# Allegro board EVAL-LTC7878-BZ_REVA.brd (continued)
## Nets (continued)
UNNAMED_3_ADLTC7878V2_I47_SW1: C82.2(N2) M17.1 M17.2 M17.3(S3) M18.5 M18.6 M18.7 M18.8 M21.1 M21.2 M21.3(S3) M22.5 M22.6 M22.7 M22.8 R79.1 R80.1 R81.1 U3.45
UNNAMED_3_ADLTC7878V2_I47_SW2: C85.1 L3.2(N2) M19.5 M19.6 M19.7 M19.8 M20.1 M20.2 M20.3(S3) M23.5 M23.6 M23.7 M23.8 M24.1 M24.2 M24.3(S3) R89.1 U3.16
UNNAMED_3_ADLTC7878V2_I47_TG1: R75.2(N2) U3.47
UNNAMED_3_ADLTC7878V2_I47_TG2: R97.2(N2) U3.14
UNNAMED_3_ADLTC7878V2_I47_VIN: C78.1 R73.2(N2) U3.4
UNNAMED_3_ADLTC7878V2_I47_VOUT: R94.2(N2) R98.1 U3.38(VOUT)
UNNAMED_3_CAP_I32_N1: C81.1 R78.2(N2)
UNNAMED_3_CAP_I94_N2: C88.2(N2) R96.2(N2) R100.1 TP47.1(N1)
UNNAMED_3_IND_I85_N1: L3.1 R80.2(N2) R81.2(N2) R82.1 R85.1
UNNAMED_3_NCTESTPAD_I107_N1: R102.2(N2) R103.1 TP54.1(N1)
UNNAMED_3_RES_I65_N1: M17.4 M21.4 R75.1
UNNAMED_3_RES_I66_N1: M18.4 M22.4 R76.1
UNNAMED_3_RES_I80_N1: M19.4 M23.4 R95.1
UNNAMED_3_RES_I109_N1: M20.4 M24.4 R97.1
UNNAMED_4_ADLTC7878V2_I126_BG1: R109.2(N2) U4.1
UNNAMED_4_ADLTC7878V2_I126_BG2: R128.2(N2) U4.12
UNNAMED_4_ADLTC7878V2_I126_BOOST1: C115.1 D7.C U4.46
UNNAMED_4_ADLTC7878V2_I126_BOOST2: C118.2(N2) D8.C U4.15
UNNAMED_4_ADLTC7878V2_I126_CSN: R129.1 TP62.1(N1) U4.35
UNNAMED_4_ADLTC7878V2_I126_CSP: C121.1 R132.1 TP67.1(N1) U4.34
UNNAMED_4_ADLTC7878V2_I126_EXTVCC: C119.1 R127.1 TP63.1(N1) U4.8
UNNAMED_4_ADLTC7878V2_I126_FREQ: R117.1 U4.28
UNNAMED_4_ADLTC7878V2_I126_ISNSD: C116.1 R116.1 R120.1 U4.43
UNNAMED_4_ADLTC7878V2_I126_ISNSN: C117.2(N2) R115.2(N2) R120.2(N2) R122.2(N2) U4.41
UNNAMED_4_ADLTC7878V2_I126_ISNSP: C116.2(N2) C117.1 R112.2(N2) R116.2(N2) R118.2(N2) U4.42
UNNAMED_4_ADLTC7878V2_I126_ITHB: R110.2(N2) U4.21
UNNAMED_4_ADLTC7878V2_I126_MODE: R121.1 R125.1 U4.26
UNNAMED_4_ADLTC7878V2_I126_PGOOD: R126.1 TP66.1(N1) U4.19
UNNAMED_4_ADLTC7878V2_I126_PHASMD: R123.1 R124.1 U4.27
UNNAMED_4_ADLTC7878V2_I126_SETCUR: R119.1 U4.31
UNNAMED_4_ADLTC7878V2_I126_SW1: C115.2(N2) M25.1 M25.2 M25.3(S3) M26.5 M26.6 M26.7 M26.8 M29.1 M29.2 M29.3(S3) M30.5 M30.6 M30.7 M30.8 R112.1 R113.1 R114.1 U4.45
UNNAMED_4_ADLTC7878V2_I126_SW2: C118.1 L4.2(N2) M27.5 M27.6 M27.7 M27.8 M28.1 M28.2 M28.3(S3) M31.5 M31.6 M31.7 M31.8 M32.1 M32.2 M32.3(S3) R122.1 U4.16
UNNAMED_4_ADLTC7878V2_I126_TG1: R108.2(N2) U4.47
UNNAMED_4_ADLTC7878V2_I126_TG2: R130.2(N2) U4.14
UNNAMED_4_ADLTC7878V2_I126_VIN: C111.1 R106.2(N2) U4.4
UNNAMED_4_ADLTC7878V2_I126_VOUT: R127.2(N2) R131.1 U4.38(VOUT)
UNNAMED_4_CAP_I32_N1: C114.1 R111.2(N2)
UNNAMED_4_CAP_I93_N2: C121.2(N2) R129.2(N2) R133.1 TP64.1(N1)
UNNAMED_4_IND_I84_N1: L4.1 R113.2(N2) R114.2(N2) R115.1 R118.1
UNNAMED_4_NCTESTPAD_I106_N1: R135.2(N2) R136.1 TP71.1(N1)
UNNAMED_4_RES_I64_N1: M25.4 M29.4 R108.1
UNNAMED_4_RES_I65_N1: M26.4 M30.4 R109.1
UNNAMED_4_RES_I79_N1: M27.4 M31.4 R128.1
UNNAMED_4_RES_I108_N1: M28.4 M32.4 R130.1
UNNAMED_5_ADLTC7878V2_I47_BG1: R142.2(N2) U5.1
UNNAMED_5_ADLTC7878V2_I47_BG2: R161.2(N2) U5.12
UNNAMED_5_ADLTC7878V2_I47_BOOST1: C148.1 D9.C U5.46
UNNAMED_5_ADLTC7878V2_I47_BOOST2: C151.2(N2) D10.C U5.15
UNNAMED_5_ADLTC7878V2_I47_CSN: R162.1 TP79.1(N1) U5.35
UNNAMED_5_ADLTC7878V2_I47_CSP: C154.1 R165.1 TP84.1(N1) U5.34
UNNAMED_5_ADLTC7878V2_I47_EXTVCC: C152.1 R160.1 TP80.1(N1) U5.8
UNNAMED_5_ADLTC7878V2_I47_FREQ: R150.1 U5.28
UNNAMED_5_ADLTC7878V2_I47_ISNSD: C149.1 R149.1 R153.1 U5.43
UNNAMED_5_ADLTC7878V2_I47_ISNSN: C150.2(N2) R148.2(N2) R153.2(N2) R155.2(N2) U5.41
UNNAMED_5_ADLTC7878V2_I47_ISNSP: C149.2(N2) C150.1 R145.2(N2) R149.2(N2) R151.2(N2) U5.42
UNNAMED_5_ADLTC7878V2_I47_ITHB: R143.2(N2) U5.21
UNNAMED_5_ADLTC7878V2_I47_MODE: R154.1 R158.1 U5.26
UNNAMED_5_ADLTC7878V2_I47_PGOOD: R159.1 TP83.1(N1) U5.19
UNNAMED_5_ADLTC7878V2_I47_PHASMD: R156.1 R157.1 U5.27
UNNAMED_5_ADLTC7878V2_I47_SETCUR: R152.1 U5.31
UNNAMED_5_ADLTC7878V2_I47_SW1: C148.2(N2) M33.1 M33.2 M33.3(S3) M34.5 M34.6 M34.7 M34.8 M37.1 M37.2 M37.3(S3) M38.5 M38.6 M38.7 M38.8 R145.1 R146.1 R147.1 U5.45
UNNAMED_5_ADLTC7878V2_I47_SW2: C151.1 L5.2(N2) M35.5 M35.6 M35.7 M35.8 M36.1 M36.2 M36.3(S3) M39.5 M39.6 M39.7 M39.8 M40.1 M40.2 M40.3(S3) R155.1 U5.16
UNNAMED_5_ADLTC7878V2_I47_TG1: R141.2(N2) U5.47
UNNAMED_5_ADLTC7878V2_I47_TG2: R163.2(N2) U5.14
UNNAMED_5_ADLTC7878V2_I47_VIN: C144.1 R139.2(N2) U5.4
UNNAMED_5_ADLTC7878V2_I47_VOUT: R160.2(N2) R164.1 U5.38(VOUT)
UNNAMED_5_CAP_I33_N1: C147.1 R144.2(N2)
UNNAMED_5_CAP_I94_N2: C154.2(N2) R162.2(N2) R166.1 TP81.1(N1)
UNNAMED_5_IND_I85_N1: L5.1 R146.2(N2) R147.2(N2) R148.1 R151.1
UNNAMED_5_NCTESTPAD_I107_N1: R168.2(N2) R169.1 TP88.1(N1)
UNNAMED_5_RES_I65_N1: M33.4 M37.4 R141.1
UNNAMED_5_RES_I66_N1: M34.4 M38.4 R142.1
UNNAMED_5_RES_I80_N1: M35.4 M39.4 R161.1
UNNAMED_5_RES_I109_N1: M36.4 M40.4 R163.1
UNNAMED_6_ADLT3014V2_I44_ADJ: R188.2(N2) R189.1 U6.4
UNNAMED_6_ADLT3014V2_I44_SHDNN: JP4.2 U6.3(SHDN_N)
UNNAMED_6_ADLTC6909_I1_MOD: JP5.1 JP5.3 JP5.5 JP5.7 U7.14
UNNAMED_6_ADLTC6909_I1_PH0: JP1.2 U7.3
UNNAMED_6_ADLTC6909_I1_PH1: JP2.2 U7.4
UNNAMED_6_ADLTC6909_I1_PH2: JP3.2 U7.15
UNNAMED_6_ADLTC6909_I1_SET: R187.2(N2) U7.16
UNNAMED_6_CAP_I32_N1: C175.1 JP5.4
VAUX: C168.2(N2) C169.2(N2) C170.2(N2) C171.1 C172.1 C173.1 C174.1 JP1.1 JP2.1 JP3.1 JP5.2 R187.1 R188.1 U6.5 U7.1 U7.13(V+D)
VFB_1: R5.1 R35.2(N2) R36.1 TP18.1(N1) U1.25
VFB_2: R5.2(N2) R65.2(N2) R66.1 R175.1 TP43.1(N1) U2.25
VFB_3: R103.2(N2) R104.1 R175.2(N2) R180.1 TP52.1(N1) U3.25
VFB_4: R136.2(N2) R137.1 R180.2(N2) R185.1 TP69.1(N1) U4.25
VFB_5: R169.2(N2) R170.1 R185.2(N2) TP86.1(N1) U5.25
VOUT: C24.1 C25.1 C26.1 C27.1 C28.1 C29.1 C30.1 C31.1 C32.P C33.P C57.1 C58.1 C59.1 C60.1 C61.1 C62.1 C63.1 C64.1 C65.P C66.P C90.1 C91.1 C92.1 C93.1 C94.1 C95.1 C96.1 C97.1 C98.P C99.P C123.1 C124.1 C125.1 C126.1 C127.1 C128.1 C129.1 C130.1 C131.P C132.P C156.1 C157.1 C158.1 C159.1 C160.1 C161.1 C162.1 C163.1 C164.P C165.P C178.P C179.P C182.P C183.P C186.P C187.P C190.P C191.P C194.P C195.P C196.1 C197.1 C198.1 C199.1 C200.1 C201.1 C202.1 C203.1 C204.1 C205.1 C208.P C209.P C212.P C213.P C216.P C217.P C220.P C221.P C224.P C225.P J3.1(N1) J7.1(N1) M4.5 M4.6 M4.7 M4.8 M8.5 M8.6 M8.7 M8.8 M12.5 M12.6 M12.7 M12.8 M16.5 M16.6 M16.7 M16.8 M20.5 M20.6 M20.7 M20.8 M24.5 M24.6 M24.7 M24.8 M28.5 M28.6 M28.7 M28.8 M32.5 M32.6 M32.7 M32.8 M36.5 M36.6 M36.7 M36.8 M40.5 M40.6 M40.7 M40.8 R31.2(N2) R32.2(N2) R33.1 R33.2(N2) R34.1 R61.2(N2) R62.2(N2) R63.1 R63.2(N2) R64.1 R68.2(N2) R71.2(N2) R98.2(N2) R99.2(N2) R100.2(N2) R101.1 R101.2(N2) R102.1 R131.2(N2) R132.2(N2) R133.2(N2) R134.1 R134.2(N2) R135.1 R164.2(N2) R165.2(N2) R166.2(N2) R167.1 R167.2(N2) R168.1 R190.1 R190.2(N2) R191.1 R191.2(N2) R192.1 R192.2(N2) R193.1 R193.2(N2) R194.1 R194.2(N2) TP19.1(N1) TP22.1(N1) TP44.1(N1) TP53.1(N1) TP70.1(N1) TP87.1(N1)

Pads without a net: U1 2 3 5 6 13 17 18 23 24 32 33 36 37 39 40 44 48; U2 2 3 5 6 13 17 18 23 24 32 33 36 37 39 40 44 48; U3 2 3 5 6 13 17 18 23 24 32 33 36 37 39 40 44 48; U4 2 3 5 6 13 17 18 23 24 32 33 36 37 39 40 44 48; U5 2 3 5 6 13 17 18 23 24 32 33 36 37 39 40 44 48; U7 10 11 12

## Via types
v1: diameter 0.508, hole 0.254, TOP to BOTTOM, 1350 vias
v2: diameter 0.305, hole 0.152, TOP to BOTTOM, 200 vias
v3: diameter 0.66, hole 0.356, TOP to BOTTOM, 1500 vias
v4: diameter 0.61, hole 0.305, TOP to BOTTOM, 320 vias

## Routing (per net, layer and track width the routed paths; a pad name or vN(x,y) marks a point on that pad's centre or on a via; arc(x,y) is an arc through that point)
SGND: length 534.8
  TOP w0.254: C147.2 v1(99.06,10.99) C146.2 ; R48.2 v1(104.27,200.53) ; v1(88.77,137.13) 88.8,137.16 C87.2 ; R74.1 89.63,134.85 90.45,134.85 C79.2 ; C112.2 90.45,73.89 89.63,73.89 R107.1 ; v1(104.27,196.47) R66.2 ; C54.2 88.8,198.12 v1(88.77,198.09) ; v1(104.27,257.43) R36.2 ; C46.2 90.45,195.81 89.63,195.81 R38.1 ; C47.2 v1(99.06,193.87) C48.2 ; v1(88.77,76.17) 88.8,76.2 C120.2 ; C113.2 v1(99.06,71.95) C114.2 ; v1(104.27,135.51) R104.2 ; R117.2 v1(104.27,78.61) ; C77.2 v1(97.03,132.84) ; v1(104.27,13.59) R170.2 ; v1(88.77,259.05) 88.8,259.08 C21.2 ; C13.2 90.45,256.77 89.63,256.77 R8.1 ; C143.2 v1(97.03,10.92) ; v1(104.27,74.55) R137.2 ; C80.2 v1(99.06,132.91) C81.2 ; C153.2 88.8,15.24 v1(88.77,15.21) ; C110.2 v1(97.03,71.88) ; R84.2 v1(104.27,139.57) ; C145.2 90.48,12.95 v1(90.04,12.95) 89.61,12.95 R140.1 ; C15.2 v1(99.06,254.83) C14.2 ; C11.2 v1(97.03,254.76) ; C44.2 v1(97.03,193.8) ; R18.2 v1(104.52,261.49) ; R150.2 v1(104.27,17.65)
  LAYER_4 w0.762: 95.57,139.26 94.42,139.26 v1(90.04,134.87) ; v1(95.89,17.75) 95.53,17.4 94.49,17.4 v1(90.04,12.95) ; v1(90.04,73.91) 94.36,78.23 95.5,78.23 ; v1(90.04,256.79) 94.49,261.24 95.5,261.24 ; 95.5,200.28 94.49,200.28 v1(90.04,195.83)
  LAYER_4 w1.27: v1(90.04,12.95) 90.04,12.19 v2(88.39,10.54) 84.33,10.54 82.42,12.45 13.59,12.45 TP74.1 ; TP31.1 25.65,195.33 79.63,195.33 81.53,193.42 v2(88.39,193.42) 90.04,195.07 v1(90.04,195.83) ; v1(90.04,73.91) 90.04,73.03 86.74,69.72 26.42,69.72 10.67,53.98 TP57.1 ; v1(90.04,256.79) 90.04,256.03 v2(88.52,254.51) 83.44,254.51 81.53,256.41 10.29,256.41 TP6.1 ; TP3.1 10.16,88.9 38.23,116.97 38.23,122.05 40.26,124.08 44.7,124.08 51.05,130.43 86.36,130.43 v2(88.52,132.59) 90.04,134.11 v1(90.04,134.87)
  LAYER_5 w0.635: 96.27,204.7 96.52,204.44 v1(96.52,202.54)
  vias: v1(95.25,263.5) v1(95.25,262.86) v1(95.25,262.23) v1(95.25,261.59) v1(95.25,260.96) v1(95.25,202.54) v1(95.25,201.9) v1(95.25,201.27) v1(95.25,200.63) v1(95.25,200) v1(95.25,141.58) v1(95.25,140.94) v1(95.25,140.31) v1(95.25,139.67) v1(95.25,139.04) v1(95.25,80.62) v1(95.25,79.98) v1(95.25,79.35) v1(95.25,78.71) v1(95.25,78.08) v1(95.25,19.66) v1(95.25,19.02) v1(95.25,18.39) v1(95.25,17.75) v1(95.25,17.12) v1(95.89,263.5) v1(95.89,262.86) v1(95.89,262.23) v1(95.89,261.59) v1(95.89,260.96) v1(95.89,202.54) v1(95.89,201.9) v1(95.89,201.27) v1(95.89,200.63) v1(95.89,200) v1(95.89,141.58) v1(95.89,140.94) v1(95.89,140.31) v1(95.89,139.67) v1(95.89,139.04) v1(95.89,80.62) v1(95.89,79.98) v1(95.89,79.35) v1(95.89,78.71) v1(95.89,78.08) v1(95.89,19.66) v1(95.89,19.02) v1(95.89,18.39) v1(95.89,17.12) v1(96.52,263.5) v1(96.52,262.86) v1(96.52,262.23) v1(96.52,261.59) v1(96.52,260.96) v1(96.52,201.9) v1(96.52,201.27) v1(96.52,200.63) v1(96.52,200) v1(96.52,141.58) v1(96.52,140.94) v1(96.52,140.31) v1(96.52,139.67) v1(96.52,139.04) v1(96.52,80.62) v1(96.52,79.98) v1(96.52,79.35) v1(96.52,78.71) v1(96.52,78.08) v1(96.52,19.66) v1(96.52,19.02) v1(96.52,18.39) v1(96.52,17.75) v1(96.52,17.12) v1(97.16,263.52) v1(97.16,262.86) v1(97.16,262.23) v1(97.16,261.59) v1(97.16,260.96) v1(97.16,202.54) v1(97.16,201.9) v1(97.16,201.27) v1(97.16,200.63) v1(97.16,200) v1(97.16,141.58) v1(97.16,140.94) v1(97.16,140.31) v1(97.16,139.67) v1(97.16,139.04) v1(97.16,80.62) v1(97.16,79.98) v1(97.16,79.35) v1(97.16,78.71) v1(97.16,78.08) v1(97.16,19.66) v1(97.16,19.02) v1(97.16,18.39) v1(97.16,17.75) v1(97.16,17.12) v1(97.79,263.5) v1(97.79,262.86) v1(97.79,262.23) v1(97.79,261.59) v1(97.79,260.96) v1(97.79,202.54) v1(97.79,201.9) v1(97.79,201.27) v1(97.79,200.63) v1(97.79,200) v1(97.79,141.58) v1(97.79,140.94) v1(97.79,140.31) v1(97.79,139.67) v1(97.79,139.04) v1(97.79,80.62) v1(97.79,79.98) v1(97.79,79.35) v1(97.79,78.71) v1(97.79,78.08) v1(97.79,19.66) v1(97.79,19.02) v1(97.79,18.39) v1(97.79,17.75) v1(97.79,17.12) v2(103.95,259.97) v2(103.95,199.01) v2(103.95,138.05) v2(103.95,77.09) v2(103.95,16.13)
VIN: length 303.5
  TOP w0.254: R6.1 v1(88.14,204.98) ; R7.1 v1(88.52,256.29) 88.52,256.26 ; v1(125.86,127.89) 125.91,127.94 C166.P ; R69.1 v1(88.14,265.94) ; R73.1 v1(88.14,144.02) ; R105.1 v1(88.52,73.41) 88.52,73.38 ; R106.1 v1(88.14,83.06) ; 88.52,195.3 v1(88.52,195.33) R37.1 ; C167.1 v1(132.72,127.64) ; R139.1 v1(88.14,22.1) ; 88.52,134.34 v1(88.52,134.37) R72.1 ; R138.1 v1(88.52,12.45)
  LAYER_4 w0.762: 78.99,122.05 v1(78.49,121.54) v1(78.49,122.05) 78.99,122.05 ; 78.99,122.05 81.79,122.05 83.19,120.65 120.02,120.65 125.86,126.49 v1(125.86,127.38) v1(125.86,127.89)
  LAYER_5 w0.254: v1(88.52,12.45) 88.52,14.48 86.74,16.26 86.74,18.41 88.14,19.81 v1(88.14,22.1) ; JP4.1 131.44,120.65 131.44,126.36 v1(132.72,127.64) ; v1(88.52,134.37) 88.52,136.14 87.88,136.78 87.88,137.67 86.74,138.81 86.74,140.46 88.14,141.86 v1(88.14,144.02) ; v1(88.52,256.29) 88.52,257.94 86.61,259.84 86.61,264.92 87.63,265.94 v1(88.14,265.94) ; v1(88.52,73.41) 88.52,75.18 86.74,76.96 86.74,79.38 88.14,80.77 v1(88.14,83.06) ; v1(88.14,204.98) 88.14,202.82 86.87,201.55 86.87,198.75 88.52,197.1 v1(88.52,195.33)
  LAYER_6 w0.381: v1(88.14,83.06) 81.92,89.28 73.53,89.28 70.23,92.58 70.23,103.89 v1(71.75,105.41) ; v1(71.75,44.45) 70.23,42.93 70.23,31.5 73.41,28.32 81.92,28.32 v1(88.14,22.1) ; v1(71.75,288.29) 70.23,286.77 70.23,275.08 75.44,269.88 86.11,269.88 88.14,267.84 v1(88.14,265.94) ; v1(88.14,204.98) 81.92,211.2 73.41,211.2 70.36,214.25 70.36,225.93 v1(71.75,227.33) ; v1(88.14,144.02) 81.92,150.24 73.28,150.24 70.23,153.29 70.23,164.85 v1(71.75,166.37)
  vias: v1(5.08,193.04) v1(5.08,177.8) v1(5.08,172.72) v1(5.08,157.48) v1(10.16,198.12) v1(10.16,193.04) v1(10.16,177.8) v1(10.16,172.72) v1(10.16,157.48) v1(15.24,304.8) v1(15.24,299.72) v1(15.24,294.64) v1(15.24,289.56) v1(15.24,284.48) v1(15.24,279.4) v1(15.24,274.32) v1(15.24,269.24) v1(15.24,264.16) v1(15.24,259.08) v1(15.24,254) v1(15.24,248.92) v1(15.24,243.84) v1(15.24,238.76) v1(15.24,233.68) v1(15.24,228.6) v1(15.24,223.52) v1(15.24,218.44) v1(15.24,213.36) v1(15.24,208.28) v1(15.24,203.2) v1(15.24,198.12) v1(15.24,193.04) v1(15.24,187.96) v1(15.24,182.88) v1(15.24,177.8) v1(15.24,172.72) v1(15.24,167.64) v1(15.24,162.56) v1(15.24,157.48) v1(15.24,152.4) v1(15.24,147.32) v1(15.24,142.24) v1(15.24,137.16) v1(15.24,132.08) v1(15.24,127) v1(15.24,121.92) v1(15.24,116.84) v1(15.24,111.76) v1(15.24,106.68) v1(15.24,101.6) v1(15.24,96.52) v1(15.24,91.44) v1(15.24,86.36) v1(15.24,81.28) v1(15.24,76.2) v1(15.24,71.12) v1(15.24,66.04) v1(15.24,60.96) v1(15.24,55.88) v1(15.24,50.8) v1(15.24,45.72) v1(20.32,304.8) v1(20.32,299.72) v1(20.32,294.64) v1(20.32,289.56) v1(20.32,284.48) v1(20.32,279.4) v1(20.32,274.32) v1(20.32,269.24) v1(20.32,264.16) v1(20.32,259.08) v1(20.32,254) v1(20.32,248.92) v1(20.32,243.84) v1(20.32,238.76) v1(20.32,233.68) v1(20.32,228.6) v1(20.32,223.52) v1(20.32,218.44) v1(20.32,213.36) v1(20.32,208.28) v1(20.32,203.2) v1(20.32,198.12) v1(20.32,193.04) v1(20.32,187.96) v1(20.32,182.88) v1(20.32,177.8) v1(20.32,172.72) v1(20.32,167.64) v1(20.32,162.56) v1(20.32,157.48) v1(20.32,152.4) v1(20.32,147.32) v1(20.32,142.24) v1(20.32,137.16) v1(20.32,132.08) v1(20.32,127) v1(20.32,121.92) v1(20.32,116.84) v1(20.32,111.76) v1(20.32,106.68) v1(20.32,101.6) v1(20.32,96.52) v1(20.32,91.44) v1(20.32,86.36) v1(20.32,81.28) v1(20.32,76.2) v1(20.32,71.12) v1(20.32,66.04) v1(20.32,60.96) v1(20.32,55.88) v1(20.32,50.8) v1(20.32,45.72) v1(25.4,304.8) v1(25.4,299.72) v1(25.4,294.64) v1(25.4,289.56) v1(25.4,284.48) v1(25.4,279.4) v1(25.4,274.32) v1(25.4,269.24) v1(25.4,264.16) v1(25.4,259.08) v1(25.4,254) v1(25.4,248.92) v1(25.4,243.84) v1(25.4,238.76) v1(25.4,233.68) v1(25.4,228.6) v1(25.4,223.52) v1(25.4,218.44) v1(25.4,213.36) v1(25.4,208.28) v1(25.4,203.2) v1(25.4,198.12) v1(25.4,193.04) v1(25.4,187.96) v1(25.4,182.88) v1(25.4,177.8) v1(25.4,172.72) v1(25.4,167.64) v1(25.4,162.56) v1(25.4,157.48) v1(25.4,152.4) v1(25.4,147.32) v1(25.4,142.24) v1(25.4,137.16) v1(25.4,132.08) v1(25.4,127) v1(25.4,121.92) v1(25.4,116.84) v1(25.4,111.76) v1(25.4,106.68) v1(25.4,101.6) v1(25.4,96.52) v1(25.4,91.44) v1(25.4,86.36) v1(25.4,81.28) v1(25.4,76.2) v1(25.4,71.12) v1(25.4,66.04) v1(25.4,60.96) v1(25.4,55.88) v1(25.4,50.8) v1(25.4,45.72) v1(30.48,304.8) v1(30.48,299.72) v1(30.48,294.64) v1(30.48,289.56) v1(30.48,284.48) v1(30.48,279.4) v1(30.48,274.32) v1(30.48,269.24) v1(30.48,264.16) v1(30.48,259.08) v1(30.48,254) v1(30.48,248.92) v1(30.48,243.84) v1(30.48,238.76) v1(30.48,233.68) v1(30.48,228.6) v1(30.48,223.52) v1(30.48,218.44) v1(30.48,213.36) v1(30.48,208.28) v1(30.48,203.2) v1(30.48,198.12) v1(30.48,193.04) v1(30.48,187.96) v1(30.48,182.88) v1(30.48,177.8) v1(30.48,172.72) v1(30.48,167.64) v1(30.48,162.56) v1(30.48,157.48) v1(30.48,152.4) v1(30.48,147.32) v1(30.48,142.24) v1(30.48,137.16) v1(30.48,132.08) v1(30.48,127) v1(30.48,121.92) v1(30.48,116.84) v1(30.48,111.76) v1(30.48,106.68) v1(30.48,101.6) v1(30.48,96.52) v1(30.48,91.44) v1(30.48,86.36) v1(30.48,81.28) v1(30.48,76.2) v1(30.48,71.12) v1(30.48,66.04) v1(30.48,60.96) v1(30.48,55.88) v1(30.48,50.8) v1(30.48,45.72) v1(35.56,304.8) v1(35.56,299.72) v1(35.56,294.64) v1(35.56,289.56) v1(35.56,284.48) v1(35.56,279.4) v1(35.56,274.32) v1(35.56,269.24) v1(35.56,264.16) v1(35.56,259.08) v1(35.56,254) v1(35.56,248.92) v1(35.56,243.84) v1(35.56,238.76) v1(35.56,233.68) v1(35.56,228.6) v1(35.56,223.52) v1(35.56,218.44) v1(35.56,213.36) v1(35.56,208.28) v1(35.56,203.2) v1(35.56,198.12) v1(35.56,193.04) v1(35.56,187.96) v1(35.56,182.88) v1(35.56,177.8) v1(35.56,172.72) v1(35.56,167.64) v1(35.56,162.56) v1(35.56,157.48) v1(35.56,152.4) v1(35.56,147.32) v1(35.56,142.24) v1(35.56,137.16) v1(35.56,132.08) v1(35.56,127) v1(35.56,121.92) v1(35.56,116.84) v1(35.56,111.76) v1(35.56,106.68) v1(35.56,101.6) v1(35.56,96.52) v1(35.56,91.44) v1(35.56,86.36) v1(35.56,81.28) v1(35.56,76.2) v1(35.56,71.12) v1(35.56,66.04) v1(35.56,60.96) v1(35.56,55.88) v1(35.56,50.8) v1(35.56,45.72) v1(40.64,304.8) v1(40.64,294.64) v1(40.64,243.84) v1(40.64,233.68) v1(40.64,182.88) v1(40.64,172.72) v1(40.64,121.92) v1(40.64,111.76) v1(40.64,60.96) v1(40.64,50.8) v1(45.72,304.8) v1(45.72,299.72) v1(45.72,294.64) v1(45.72,289.56) v1(45.72,243.84) v1(45.72,238.76) v1(45.72,233.68) v1(45.72,228.6) v1(45.72,182.88) v1(45.72,177.8) v1(45.72,172.72) v1(45.72,167.64) v1(45.72,121.92) v1(45.72,116.84) v1(45.72,111.76) v1(45.72,106.68) v1(45.72,60.96) v1(45.72,55.88) v1(45.72,50.8) v1(45.72,45.72) v1(50.8,304.8) v1(50.8,299.72) v1(50.8,294.64) v1(50.8,289.56) v1(50.8,243.84) v1(50.8,238.76) v1(50.8,233.68) v1(50.8,228.6) v1(50.8,182.88) v1(50.8,177.8) v1(50.8,172.72) v1(50.8,167.64) v1(50.8,121.92) v1(50.8,116.84) v1(50.8,111.76) v1(50.8,106.68) v1(50.8,60.96) v1(50.8,55.88) v1(50.8,50.8) v1(50.8,45.72) v1(55.88,304.8) v1(55.88,294.64) v1(55.88,243.84) v1(55.88,233.68) v1(55.88,182.88) v1(55.88,172.72) v1(55.88,121.92) v1(55.88,111.76) v1(55.88,60.96) v1(55.88,50.8) v1(60.96,304.8) v1(60.96,299.72) v1(60.96,294.64) v1(60.96,243.84) v1(60.96,238.76) v1(60.96,233.68) v1(60.96,182.88) v1(60.96,177.8) v1(60.96,172.72) v1(60.96,121.92) v1(60.96,116.84) v1(60.96,111.76) v1(60.96,60.96) v1(60.96,55.88) v1(60.96,50.8) v1(61.34,289.94) v1(61.34,228.98) v1(61.34,168.02) v1(61.34,107.06) v1(61.34,46.1) v1(61.85,289.94) v1(61.85,228.98) v1(61.85,168.02) v1(61.85,107.06) v1(61.85,46.1) v1(62.36,289.94) v1(62.36,228.98) v1(62.36,168.02) v1(62.36,107.06) v1(62.36,46.1) v1(64.64,289.94) v1(64.64,228.98) v1(64.64,168.02) v1(64.64,107.06) v1(64.64,46.1) v1(65.15,289.94) v1(65.15,228.98) v1(65.15,168.02) v1(65.15,107.06) v1(65.15,46.1) v1(65.66,289.94) v1(65.66,228.98) v1(65.66,168.02) v1(65.66,107.06) v1(65.66,46.1) v1(66.04,304.8) v1(66.04,299.72) v1(66.04,294.64) v1(66.04,243.84) v1(66.04,238.76) v1(66.04,233.68) v1(66.04,182.88) v1(66.04,177.8) v1(66.04,172.72) v1(66.04,121.92) v1(66.04,116.84) v1(66.04,111.76) v1(66.04,60.96) v1(66.04,55.88) v1(66.04,50.8) v1(67.94,289.94) v1(67.94,228.98) v1(67.94,168.02) v1(67.94,107.06) v1(67.94,46.1) v1(68.45,289.94) v1(68.45,228.98) v1(68.45,168.02) v1(68.45,107.06) v1(68.45,46.1) v1(68.96,289.94) v1(68.96,228.98) v1(68.96,168.02) v1(68.96,107.06) v1(68.96,46.1) v1(71.12,304.8) v1(71.12,299.72) v1(71.12,294.64) v1(71.12,243.84) v1(71.12,238.76) v1(71.12,233.68) v1(71.12,182.88) v1(71.12,177.8) v1(71.12,172.72) v1(71.12,121.92) v1(71.12,116.84) v1(71.12,111.76) v1(71.12,60.96) v1(71.12,55.88) v1(71.12,50.8) v1(71.25,289.94) v1(71.25,228.98) v1(71.25,168.02) v1(71.25,107.06) v1(71.25,46.1) v1(71.75,289.94) v1(71.75,228.98) v1(71.75,168.02) v1(71.75,107.06) v1(71.75,46.1) v1(72.26,289.94) v1(72.26,228.98) v1(72.26,168.02) v1(72.26,107.06) v1(72.26,46.1) v1(76.2,304.8) v1(76.2,299.72) v1(76.2,294.64) v1(76.2,243.84) v1(76.2,238.76) v1(76.2,233.68) v1(76.2,182.88) v1(76.2,177.8) v1(76.2,172.72) v1(76.2,121.92) v1(76.2,116.84) v1(76.2,111.76) v1(76.2,60.96) v1(76.2,55.88) v1(76.2,50.8) v3(41.02,302.39) v3(41.02,300.86) v3(41.02,299.34) v3(41.02,291.97) v3(41.02,290.45) v3(41.02,288.93) v3(41.02,242.06) v3(41.02,240.54) v3(41.02,239.01) v3(41.02,231.01) v3(41.02,229.49) v3(41.02,227.97) v3(41.02,180.97) v3(41.02,179.45) v3(41.02,177.93) v3(41.02,170.05) v3(41.02,168.53) v3(41.02,167) v3(41.02,120.02) v3(41.02,118.49) v3(41.02,116.97) v3(41.02,109.09) v3(41.02,107.57) v3(41.02,106.05) v3(41.02,59.05) v3(41.02,57.53) v3(41.02,56.01) v3(41.02,48.13) v3(41.02,46.61) v3(41.02,45.09) v3(44.07,302.39) v3(44.07,300.86) v3(44.07,299.34) v3(44.07,291.97) v3(44.07,290.45) v3(44.07,288.93) v3(44.07,242.06) v3(44.07,240.54) v3(44.07,239.01) v3(44.07,231.01) v3(44.07,229.49) v3(44.07,227.97) v3(44.07,180.97) v3(44.07,179.45) v3(44.07,177.93) v3(44.07,170.05) v3(44.07,168.53) v3(44.07,167) v3(44.07,120.02) v3(44.07,118.49) v3(44.07,116.97) v3(44.07,109.09) v3(44.07,107.57) v3(44.07,106.05) v3(44.07,59.05) v3(44.07,57.53) v3(44.07,56.01) v3(44.07,48.13) v3(44.07,46.61) v3(44.07,45.09) v3(52.45,302.39) v3(52.45,300.86) v3(52.45,299.34) v3(52.45,291.97) v3(52.45,290.45) v3(52.45,288.93) v3(52.45,241.94) v3(52.45,240.41) v3(52.45,238.89) v3(52.45,231.01) v3(52.45,229.49) v3(52.45,227.97) v3(52.45,180.97) v3(52.45,179.45) v3(52.45,177.93) v3(52.45,170.05) v3(52.45,168.53) v3(52.45,167) v3(52.45,120.02) v3(52.45,118.49) v3(52.45,116.97) v3(52.45,109.09) v3(52.45,107.57) v3(52.45,106.05) v3(52.45,59.05) v3(52.45,57.53) v3(52.45,56.01) v3(52.45,48.13) v3(52.45,46.61) v3(52.45,45.09) v3(55.5,302.39) v3(55.5,300.86) v3(55.5,299.34) v3(55.5,291.97) v3(55.5,290.45) v3(55.5,288.93) v3(55.5,241.94) v3(55.5,240.41) v3(55.5,238.89) v3(55.5,231.01) v3(55.5,229.49) v3(55.5,227.97) v3(55.5,180.97) v3(55.5,179.45) v3(55.5,177.93) v3(55.5,170.05) v3(55.5,168.53) v3(55.5,167) v3(55.5,120.02) v3(55.5,118.49) v3(55.5,116.97) v3(55.5,109.09) v3(55.5,107.57) v3(55.5,106.05) v3(55.5,59.05) v3(55.5,57.53) v3(55.5,56.01) v3(55.5,48.13) v3(55.5,46.61) v3(55.5,45.09) v4(74.55,291.85) v4(74.55,290.58) v4(74.55,289.31) v4(74.55,288.04) v4(74.55,230.89) v4(74.55,229.62) v4(74.55,228.35) v4(74.55,227.08) v4(74.55,169.93) v4(74.55,168.66) v4(74.55,167.39) v4(74.55,166.12) v4(74.55,108.97) v4(74.55,107.7) v4(74.55,106.43) v4(74.55,105.16) v4(74.55,48.01) v4(74.55,46.74) v4(74.55,45.47) v4(74.55,44.2) v4(75.82,291.85) v4(75.82,290.58) v4(75.82,289.31) v4(75.82,288.04) v4(75.82,230.89) v4(75.82,229.62) v4(75.82,228.35) v4(75.82,227.08) v4(75.82,169.93) v4(75.82,168.66) v4(75.82,167.39) v4(75.82,166.12) v4(75.82,108.97) v4(75.82,107.7) v4(75.82,106.43) v4(75.82,105.16) v4(75.82,48.01) v4(75.82,46.74) v4(75.82,45.47) v4(75.82,44.2) v4(77.09,291.85) v4(77.09,290.58) v4(77.09,289.31) v4(77.09,288.04) v4(77.09,230.89) v4(77.09,229.62) v4(77.09,228.35) v4(77.09,227.08) v4(77.09,169.93) v4(77.09,168.66) v4(77.09,167.39) v4(77.09,166.12) v4(77.09,108.97) v4(77.09,107.7) v4(77.09,106.43) v4(77.09,105.16) v4(77.09,48.01) v4(77.09,46.74) v4(77.09,45.47) v4(77.09,44.2) v4(78.36,291.85) v4(78.36,290.58) v4(78.36,289.31) v4(78.36,288.04) v4(78.36,230.89) v4(78.36,229.62) v4(78.36,228.35) v4(78.36,227.08) v4(78.36,169.93) v4(78.36,168.66) v4(78.36,167.39) v4(78.36,166.12) v4(78.36,108.97) v4(78.36,107.7) v4(78.36,106.43) v4(78.36,105.16) v4(78.36,48.01) v4(78.36,46.74) v4(78.36,45.47) v4(78.36,44.2)
CLKOUT_1: length 81.7
  TOP w0.254: U1.29 100.95,261.5 v2(100.97,261.49)
  LAYER_4 w0.254: v2(115.19,263.27) 145.8,263.27 146.34,262.72 177.33,262.72 TP8.1
  LAYER_6 w0.254: v2(100.97,261.49) 101.98,261.49 103.5,263.02 114.94,263.02 v2(115.19,263.27)
CLKOUT_2: length 86.8
  TOP w0.254: U2.29 100.95,200.54 v2(100.97,200.53)
  LAYER_4 w0.254: TP33.1 130.68,215.26 121.03,205.61 121.03,204.05 v2(120.06,203.07)
  LAYER_6 w0.254: v2(100.97,200.53) 102.17,200.53 103.76,202.12 119.1,202.12 v2(120.06,203.07)
CLKOUT_3: length 105.6
  TOP w0.254: U3.29 100.95,139.58 v2(100.97,139.57)
  LAYER_4 w0.254: TP24.1 179.71,93.22 144.4,128.52 v2(144.4,129.92)
  LAYER_6 w0.254: v2(144.4,129.92) 124.97,129.92 118.36,136.53 113.54,136.53 108.84,141.22 103.89,141.22 102.23,139.57 v2(100.97,139.57)
CLKOUT_4: length 91.3
  TOP w0.254: v2(100.97,78.61) 100.95,78.62 U4.29
  LAYER_5 w0.254: v2(123.63,77.03) 156.53,77.03 TP59.1
  LAYER_6 w0.254: v2(100.97,78.61) 102.11,78.61 103.63,80.14 105.22,80.14 105.82,79.53 114.97,79.53 117.47,77.03 v2(123.63,77.03)
CLKOUT_5: length 80.8
  TOP w0.254: U5.29 100.95,17.66 v2(100.97,17.65)
  LAYER_4 w0.254: v2(116.84,19.3) 176.15,19.3 177.04,20.19 TP76.1
  LAYER_6 w0.254: v2(116.84,19.3) 116.77,19.24 103.63,19.24 102.04,17.65 v2(100.97,17.65)
DRVCC_1: length 34.2
  TOP w0.254: v2(90.93,255.02) D2.A ; D1.A v2(90.04,267.72) ; C23.1 90.51,262.86 90.93,262.86 91,262.93 ; U1.7 91.94,262.01 v2(91,262.95) ; v2(78.99,266.95) TP17.1
  LAYER_4 w0.254: v2(78.99,266.95) 83.06,266.95 86.49,263.52 90.42,263.52 v2(91,262.95)
  LAYER_6 w0.254: v2(90.93,255.02) 90.55,255.02 89.41,256.16 89.41,258 89.85,258.44 89.85,259.52 91.88,261.56 91.88,262.38 91.31,262.95 v2(91,262.95) 91,266.76 v2(90.04,267.72)
DRVCC_2: length 34.3
  TOP w0.254: v2(78.99,205.99) TP42.1 ; D3.A v2(90.04,206.76) ; U2.7 91.94,201.05 v2(91,201.99) ; C56.1 90.51,201.9 90.93,201.9 91,201.97 ; v2(90.93,194.06) D4.A
  LAYER_4 w0.254: v2(78.99,205.99) 83.06,205.99 86.49,202.56 90.42,202.56 v2(91,201.99)
  LAYER_6 w0.254: v2(90.93,194.06) 90.68,194.06 89.41,195.33 89.41,196.85 89.92,197.36 89.92,198.63 91.95,200.66 91.95,201.42 91.38,201.99 v2(91,201.99) 91,205.8 v2(90.04,206.76)
DRVCC_3: length 34.3
  TOP w0.254: v2(90.93,133.1) D6.A ; U3.7 91.94,140.09 v2(91,141.03) ; v2(78.99,145.03) TP51.1 ; C89.1 90.51,140.94 90.93,140.94 91,141.01 ; D5.A v2(90.04,145.8)
  LAYER_4 w0.254: v2(78.99,145.03) 83.06,145.03 86.49,141.6 90.42,141.6 v2(91,141.03)
  LAYER_6 w0.254: v2(90.04,145.8) 91,144.84 v2(91,141.03) 91.5,141.03 91.95,140.59 91.95,139.45 89.92,137.41 89.92,136.65 89.41,136.14 89.41,134.49 90.81,133.1 v2(90.93,133.1)
DRVCC_4: length 34.4
  TOP w0.254: D7.A v2(90.04,84.84) ; v2(91,80.07) 91.94,79.13 U4.7 ; 91,80.05 90.93,79.98 90.51,79.98 C122.1 ; v2(78.99,84.07) TP68.1 ; v2(90.93,72.14) D8.A
  LAYER_4 w0.254: v2(78.99,84.07) 83.06,84.07 86.49,80.64 90.42,80.64 v2(91,80.07)
  LAYER_6 w0.254: v2(90.04,84.84) 91,83.88 v2(91,80.07) 91.38,80.07 91.95,79.5 91.95,78.49 89.98,76.52 89.98,75.44 89.41,74.87 89.41,73.15 90.42,72.14 v2(90.93,72.14)
DRVCC_5: length 34.4
  TOP w0.254: v2(91,19.11) 91.94,18.17 U5.7 ; C155.1 90.51,19.02 90.93,19.02 91,19.09 ; D9.A v2(90.04,23.88) ; v2(78.99,23.11) TP85.1 ; v2(90.93,11.18) D10.A
  LAYER_4 w0.254: v2(91,19.11) 90.42,19.68 86.49,19.68 83.06,23.11 v2(78.99,23.11)
  LAYER_6 w0.254: v2(90.04,23.88) 91,22.92 v2(91,19.11) 91.44,19.11 91.95,18.61 91.95,17.53 89.92,15.49 89.92,14.35 89.34,13.78 89.34,12.51 90.68,11.18 v2(90.93,11.18)
GROUND: length 71
  TOP w0.254: v1(115.32,152.65) C97.2 115.32,153.7 ; v1(115.32,152.65) v1(115.82,152.65) ; v1(115.32,152.65) v1(114.81,152.65) ; v1(121.41,213.61) v1(121.92,213.61) ; v1(121.92,213.61) C60.2 121.92,214.66 ; v1(121.92,213.61) v1(122.43,213.61) ; C171.2 v1(139.83,126.11) ; v1(124.71,213.61) v1(125.22,213.61) ; v1(125.22,213.61) C57.2 125.22,214.66 ; v1(125.22,213.61) v1(125.73,213.61) ; v1(118.62,152.65) C95.2 118.62,153.7 ; v1(118.62,152.65) v1(118.11,152.65) ; v1(118.62,152.65) v1(119.13,152.65) ; v1(121.41,274.57) v1(121.92,274.57) ; v1(121.92,274.57) v1(122.43,274.57) ; v1(121.92,274.57) C30.2 121.92,275.62 ; v1(115.82,274.57) v1(115.32,274.57) ; v1(115.32,274.57) C28.2 115.32,275.62 ; v1(115.32,274.57) v1(114.81,274.57) ; v1(114.81,91.69) v1(115.32,91.69) ; v1(115.32,91.69) C130.2 115.32,92.74 ; v1(115.32,91.69) v1(115.82,91.69) ; v1(115.32,213.61) C63.2 115.32,214.66 ; v1(115.32,213.61) v1(114.81,213.61) ; v1(115.32,213.61) v1(115.82,213.61) ; 125.22,153.7 C91.2 v1(125.22,152.65) ; v1(87.5,81.79) 88.1,81.79 C111.2 88.15,81.28 v1(87.5,81.28) ; v1(114.81,30.73) v1(115.32,30.73) ; v1(115.32,30.73) C163.2 115.32,31.78 ; v1(115.32,30.73) v1(115.82,30.73) ; v1(118.11,30.73) v1(118.62,30.73) ; v1(118.62,30.73) v1(119.13,30.73) ; v1(118.62,30.73) C161.2 118.62,31.78 ; v1(125.73,30.73) v1(125.22,30.73) ; v1(125.22,30.73) C157.2 125.22,31.78 ; v1(125.22,30.73) v1(124.71,30.73) ; v1(118.11,213.61) v1(118.62,213.61) ; v1(118.62,213.61) v1(119.13,213.61) ; v1(118.62,213.61) C58.2 118.62,214.66 ; 121.92,31.78 C160.2 v1(121.92,30.73) ; 118.62,275.62 C29.2 v1(118.62,274.57) ; v1(122.43,30.73) v1(121.92,30.73) ; v1(121.92,30.73) v1(121.41,30.73) ; v1(87.5,200.28) 88.13,200.28 C53.2 88.13,200.79 v1(87.5,200.79) ; v1(87.5,78.36) 88.13,78.36 C119.2 88.13,78.87 v1(87.5,78.87) ; v1(124.71,274.57) v1(125.22,274.57) ; v1(125.22,274.57) C27.2 125.22,275.62 ; v1(125.22,274.57) v1(125.73,274.57) ; v1(118.11,274.57) v1(118.62,274.57) ; v1(118.62,274.57) v1(119.13,274.57) ; v1(125.73,152.65) v1(125.22,152.65) ; v1(125.22,152.65) v1(124.71,152.65) ; R189.2 v1(135.89,125.09) ; v1(122.43,91.69) v1(121.92,91.69) ; v1(121.92,91.69) v1(121.41,91.69) ; v1(121.92,91.69) C127.2 121.92,92.74 ; v1(88.77,140.97) C89.2 ; v1(137.41,135.51) C170.1 137.38,134.89 U7.2 ; 118.62,92.74 C128.2 v1(118.62,91.69) ; v1(87.5,20.32) 88.15,20.32 C144.2 88.1,20.83 v1(87.5,20.83) ; v1(87.5,17.91) 88.13,17.91 C152.2 88.13,17.4 v1(87.5,17.4) ; 121.92,153.7 C94.2 v1(121.92,152.65) ; v1(88.77,201.93) C56.2 ; v1(121.41,152.65) v1(121.92,152.65) ; v1(121.92,152.65) v1(122.43,152.65) ; v1(88.77,19.05) C155.2 ; v1(87.5,142.75) 88.1,142.75 C78.2 88.15,142.24 v1(87.5,142.24) ; v1(125.22,91.69) C124.2 125.22,92.74 ; v1(125.22,91.69) v1(124.71,91.69) ; v1(125.22,91.69) v1(125.73,91.69) ; v1(87.5,261.75) 88.13,261.75 C20.2 88.13,261.24 v1(87.5,261.24) ; v1(87.5,264.67) 88.1,264.67 C12.2 88.15,264.16 v1(87.5,264.16) ; C172.2 v1(141.1,126.11) ; C169.1 v1(138.43,135.51) ; v1(87.5,139.83) 88.13,139.83 C86.2 88.13,139.32 v1(87.5,139.32) ; v1(118.62,91.69) v1(118.11,91.69) ; v1(118.62,91.69) v1(119.13,91.69) ; C173.2 v1(127.64,135.89) ; v1(87.5,203.71) 88.1,203.71 C45.2 88.15,203.2 v1(87.5,203.2) ; U6.2 v1(136.91,127.51) ; C174.2 v1(127.64,134.87) ; v1(88.77,80.01) C122.2 ; v1(88.77,262.89) C23.2
  vias: v1(61.34,284.99) v1(61.34,224.03) v1(61.34,163.07) v1(61.34,102.11) v1(61.34,41.15) v1(61.85,284.99) v1(61.85,224.03) v1(61.85,163.07) v1(61.85,102.11) v1(61.85,41.15) v1(62.36,284.99) v1(62.36,224.03) v1(62.36,163.07) v1(62.36,102.11) v1(62.36,41.15) v1(64.64,284.99) v1(64.64,224.03) v1(64.64,163.07) v1(64.64,102.11) v1(64.64,41.15) v1(65.15,284.99) v1(65.15,224.03) v1(65.15,163.07) v1(65.15,102.11) v1(65.15,41.15) v1(65.66,284.99) v1(65.66,224.03) v1(65.66,163.07) v1(65.66,102.11) v1(65.66,41.15) v1(67.94,284.99) v1(67.94,224.03) v1(67.94,163.07) v1(67.94,102.11) v1(67.94,41.15) v1(68.45,284.99) v1(68.45,224.03) v1(68.45,163.07) v1(68.45,102.11) v1(68.45,41.15) v1(68.96,284.99) v1(68.96,224.03) v1(68.96,163.07) v1(68.96,102.11) v1(68.96,41.15) v1(71.25,284.99) v1(71.25,224.03) v1(71.25,163.07) v1(71.25,102.11) v1(71.25,41.15) v1(71.75,284.99) v1(71.75,224.03) v1(71.75,163.07) v1(71.75,102.11) v1(71.75,41.15) v1(72.26,284.99) v1(72.26,224.03) v1(72.26,163.07) v1(72.26,102.11) v1(72.26,41.15) v1(125.86,123.57) v1(125.86,122.56) v1(125.86,121.67) v1(128.14,123.57) v1(128.14,122.68) v1(128.14,121.67) v1(132.21,124.71) v1(132.72,124.71) v1(133.22,124.71) v1(134.75,274.57) v1(134.87,213.61) v1(134.87,152.53) v1(134.87,91.69) v1(134.87,30.73) v1(135.25,274.57) v1(135.38,213.61) v1(135.38,152.53) v1(135.38,91.69) v1(135.38,30.73) v1(135.76,274.57) v1(135.89,213.61) v1(135.89,152.53) v1(135.89,91.69) v1(135.89,30.73) v1(138.3,274.57) v1(138.43,213.61) v1(138.43,152.53) v1(138.43,91.69) v1(138.43,30.73) v1(138.81,274.57) v1(138.94,213.61) v1(138.94,152.53) v1(138.94,91.69) v1(138.94,30.73) v1(139.32,274.57) v1(139.45,213.61) v1(139.45,152.53) v1(139.45,91.69) v1(139.45,30.73) v1(140.08,138.18) v1(140.59,138.18) v2(91.69,13.34) v2(91.69,12.95) v2(92.08,257.56) v2(92.08,257.18) v2(92.08,196.47) v2(92.08,196.09) v2(92.08,135.38) v2(92.08,135) v2(92.08,74.42) v2(92.08,74.04) v3(1.65,307.34) v3(1.65,302.26) v3(1.65,297.18) v3(1.65,292.1) v3(1.65,287.02) v3(1.65,281.94) v3(1.65,276.86) v3(1.65,271.78) v3(1.65,266.7) v3(1.65,261.62) v3(1.65,256.54) v3(1.65,251.46) v3(1.65,246.38) v3(1.65,241.3) v3(1.65,231.14) v3(1.65,226.06) v3(1.65,220.98) v3(1.65,215.9) v3(1.65,210.82) v3(1.65,205.74) v3(1.65,200.66) v3(1.65,195.58) v3(1.65,190.5) v3(1.65,185.42) v3(1.65,180.34) v3(1.65,175.26) v3(1.65,170.18) v3(1.65,165.1) v3(1.65,160.02) v3(1.65,154.94) v3(1.65,149.86) v3(1.65,144.78) v3(1.65,139.7) v3(1.65,134.62) v3(1.65,129.54) v3(1.65,124.46) v3(1.65,119.38) v3(1.65,114.3) v3(1.65,109.22) v3(1.65,104.14) v3(1.65,99.06) v3(1.65,93.98) v3(1.65,88.9) v3(1.65,83.82) v3(1.65,78.74) v3(1.65,73.66) v3(1.65,68.58) v3(1.65,63.5) v3(1.65,58.42) v3(1.65,53.34) v3(1.65,48.26) v3(1.65,43.18) v3(1.65,38.1) v3(1.65,33.02) v3(1.65,27.94) v3(1.65,22.86) v3(1.65,17.78) v3(1.65,12.7) v3(5.08,304.8) v3(5.08,299.72) v3(5.08,294.64) v3(5.08,289.56) v3(5.08,284.48) v3(5.08,279.4) v3(5.08,274.32) v3(5.08,254) v3(5.08,248.92) v3(5.08,243.84) v3(5.08,228.6) v3(5.08,208.28) v3(5.08,203.2) v3(5.08,149.86) v3(5.08,147.32) v3(5.08,134.62) v3(5.08,132.08) v3(5.08,127) v3(5.08,124.46) v3(5.08,111.76) v3(5.08,109.22) v3(5.08,101.6) v3(5.08,86.36) v3(5.08,81.28) v3(5.08,71.12) v3(5.08,66.04) v3(5.08,50.8) v3(5.08,45.72) v3(5.08,40.64) v3(5.08,35.56) v3(7.62,149.86) v3(7.62,147.32) v3(7.62,134.62) v3(7.62,132.08) v3(7.62,127) v3(7.62,124.46) v3(7.62,111.76) v3(7.62,109.22) v3(10.16,315.85) v3(10.16,309.88) v3(10.16,304.8) v3(10.16,299.72) v3(10.16,294.64) v3(10.16,289.56) v3(10.16,284.48) v3(10.16,279.4) v3(10.16,274.32) v3(10.16,269.24) v3(10.16,264.16) v3(10.16,259.08) v3(10.16,254) v3(10.16,248.92) v3(10.16,243.84) v3(10.16,238.76) v3(10.16,233.68) v3(10.16,228.6) v3(10.16,223.52) v3(10.16,218.44) v3(10.16,213.36) v3(10.16,208.28) v3(10.16,203.2) v3(10.16,149.86) v3(10.16,147.32) v3(10.16,134.62) v3(10.16,132.08) v3(10.16,127) v3(10.16,124.46) v3(10.16,111.76) v3(10.16,109.22) v3(10.16,106.68) v3(10.16,101.6) v3(10.16,96.52) v3(10.16,91.44) v3(10.16,86.36) v3(10.16,81.28) v3(10.16,76.2) v3(10.16,71.12) v3(10.16,66.04) v3(10.16,60.96) v3(10.16,55.88) v3(10.16,50.8) v3(10.16,45.72) v3(10.16,40.64) v3(10.16,35.56) v3(10.16,30.48) v3(10.16,10.16) v3(10.16,5.08) v3(10.16,1.65) v3(12.7,149.86) v3(12.7,147.32) v3(12.7,134.62) v3(12.7,132.08) v3(12.7,127) v3(12.7,124.46) v3(12.7,111.76) v3(12.7,109.22) v3(15.24,315.85) v3(15.24,309.88) v3(15.24,40.64) v3(15.24,35.56) v3(15.24,30.48) v3(15.24,25.4) v3(15.24,20.32) v3(15.24,15.24) v3(15.24,10.16) v3(15.24,5.08) v3(15.24,1.65) v3(20.32,315.85) v3(20.32,309.88) v3(20.32,40.64) v3(20.32,35.56) v3(20.32,30.48) v3(20.32,25.4) v3(20.32,20.32) v3(20.32,15.24) v3(20.32,10.16) v3(20.32,5.08) v3(20.32,1.65) v3(25.4,315.85) v3(25.4,309.88) v3(25.4,40.64) v3(25.4,35.56) v3(25.4,30.48) v3(25.4,25.4) v3(25.4,20.32) v3(25.4,15.24) v3(25.4,10.16) v3(25.4,5.08) v3(25.4,1.65) v3(30.48,315.85) v3(30.48,309.88) v3(30.48,40.64) v3(30.48,35.56) v3(30.48,30.48) v3(30.48,25.4) v3(30.48,20.32) v3(30.48,15.24) v3(30.48,10.16) v3(30.48,5.08) v3(30.48,1.65) v3(35.56,315.85) v3(35.56,309.88) v3(35.56,40.64) v3(35.56,35.56) v3(35.56,30.48) v3(35.56,25.4) v3(35.56,20.32) v3(35.56,15.24) v3(35.56,10.16) v3(35.56,5.08) v3(35.56,1.65) v3(40.64,315.85) v3(40.64,274.32) v3(40.64,269.24) v3(40.64,264.16) v3(40.64,259.08) v3(40.64,254) v3(40.64,213.36) v3(40.64,208.28) v3(40.64,203.2) v3(40.64,198.12) v3(40.64,193.04) v3(40.64,152.4) v3(40.64,147.32) v3(40.64,142.24) v3(40.64,137.16) v3(40.64,91.44) v3(40.64,86.36) v3(40.64,81.28) v3(40.64,71.12) v3(40.64,30.48) v3(40.64,25.4) v3(40.64,20.32) v3(40.64,15.24) v3(40.64,10.16) v3(40.64,5.08) v3(40.64,1.65) v3(41.02,311.66) v3(41.02,310.13) v3(41.02,308.61) v3(41.02,283.59) v3(41.02,282.07) v3(41.02,280.54) v3(41.02,251.33) v3(41.02,249.81) v3(41.02,248.28) v3(41.02,222.63) v3(41.02,221.11) v3(41.02,219.58) v3(41.02,190.37) v3(41.02,188.85) v3(41.02,187.32) v3(41.02,161.67) v3(41.02,160.15) v3(41.02,158.62) v3(41.02,129.16) v3(41.02,127.64) v3(41.02,126.11) v3(41.02,100.71) v3(41.02,99.19) v3(41.02,97.66) v3(41.02,68.45) v3(41.02,66.93) v3(41.02,65.41) v3(41.02,39.75) v3(41.02,38.23) v3(41.02,36.7) v3(44.07,311.66) v3(44.07,310.13) v3(44.07,308.61) v3(44.07,283.59) v3(44.07,282.07) v3(44.07,280.54) v3(44.07,251.33) v3(44.07,249.81) v3(44.07,248.28) v3(44.07,222.63) v3(44.07,221.11) v3(44.07,219.58) v3(44.07,190.37) v3(44.07,188.85) v3(44.07,187.32) v3(44.07,161.67) v3(44.07,160.15) v3(44.07,158.62) v3(44.07,129.16) v3(44.07,127.64) v3(44.07,126.11) v3(44.07,100.71) v3(44.07,99.19) v3(44.07,97.66) v3(44.07,68.45) v3(44.07,66.93) v3(44.07,65.41) v3(44.07,39.75) v3(44.07,38.23) v3(44.07,36.7) v3(45.72,315.85) v3(45.72,274.32) v3(45.72,269.24) v3(45.72,264.16) v3(45.72,259.08) v3(45.72,254) v3(45.72,213.36) v3(45.72,208.28) v3(45.72,203.2) v3(45.72,198.12) v3(45.72,193.04) v3(45.72,152.4) v3(45.72,147.32) v3(45.72,142.24) v3(45.72,137.16) v3(45.72,91.44) v3(45.72,86.36) v3(45.72,81.28) v3(45.72,71.12) v3(45.72,30.48) v3(45.72,25.4) v3(45.72,20.32) v3(45.72,15.24) v3(45.72,10.16) v3(45.72,5.08) v3(45.72,1.65) v3(50.8,315.85) v3(50.8,274.32) v3(50.8,269.24) v3(50.8,264.16) v3(50.8,259.08) v3(50.8,254) v3(50.8,218.44) v3(50.8,213.36) v3(50.8,208.28) v3(50.8,203.2) v3(50.8,198.12) v3(50.8,193.04) v3(50.8,152.4) v3(50.8,147.32) v3(50.8,142.24) v3(50.8,91.44) v3(50.8,86.36) v3(50.8,81.28) v3(50.8,71.12) v3(50.8,30.48) v3(50.8,25.4) v3(50.8,20.32) v3(50.8,15.24) v3(50.8,10.16) v3(50.8,5.08) v3(50.8,1.65) v3(52.45,311.66) v3(52.45,310.13) v3(52.45,308.61) v3(52.45,283.59) v3(52.45,282.07) v3(52.45,280.54) v3(52.45,251.33) v3(52.45,249.81) v3(52.45,248.28) v3(52.45,222.63) v3(52.45,221.11) v3(52.45,219.58) v3(52.45,190.5) v3(52.45,188.98) v3(52.45,187.45) v3(52.45,161.67) v3(52.45,160.15) v3(52.45,158.62) v3(52.45,129.16) v3(52.45,127.64) v3(52.45,126.11) v3(52.45,100.71) v3(52.45,99.19) v3(52.45,97.66) v3(52.45,68.45) v3(52.45,66.93) v3(52.45,65.41) v3(52.45,39.75) v3(52.45,38.23) v3(52.45,36.7) v3(55.5,311.66) v3(55.5,310.13) v3(55.5,308.61) v3(55.5,283.59) v3(55.5,282.07) v3(55.5,280.54) v3(55.5,251.33) v3(55.5,249.81) v3(55.5,248.28) v3(55.5,222.63) v3(55.5,221.11) v3(55.5,219.58) v3(55.5,190.5) v3(55.5,188.98) v3(55.5,187.45) v3(55.5,161.67) v3(55.5,160.15) v3(55.5,158.62) v3(55.5,129.16) v3(55.5,127.64) v3(55.5,126.11) v3(55.5,100.71) v3(55.5,99.19) v3(55.5,97.66) v3(55.5,68.45) v3(55.5,66.93) v3(55.5,65.41) v3(55.5,39.75) v3(55.5,38.23) v3(55.5,36.7) v3(55.88,315.85) v3(55.88,274.32) v3(55.88,269.24) v3(55.88,264.16) v3(55.88,259.08) v3(55.88,254) v3(55.88,213.36) v3(55.88,208.28) v3(55.88,203.2) v3(55.88,198.12) v3(55.88,193.04) v3(55.88,152.4) v3(55.88,147.32) v3(55.88,142.24) v3(55.88,137.16) v3(55.88,132.08) v3(55.88,91.44) v3(55.88,86.36) v3(55.88,81.28) v3(55.88,71.12) v3(55.88,30.48) v3(55.88,25.4) v3(55.88,20.32) v3(55.88,15.24) v3(55.88,10.16) v3(55.88,5.08) v3(55.88,1.65) v3(60.96,315.85) v3(60.96,309.88) v3(60.96,279.4) v3(60.96,274.32) v3(60.96,269.24) v3(60.96,264.16) v3(60.96,259.08) v3(60.96,254) v3(60.96,248.92) v3(60.96,218.44) v3(60.96,213.36) v3(60.96,208.28) v3(60.96,203.2) v3(60.96,198.12) v3(60.96,193.04) v3(60.96,187.96) v3(60.96,157.48) v3(60.96,152.4) v3(60.96,147.32) v3(60.96,142.24) v3(60.96,137.16) v3(60.96,132.08) v3(60.96,127) v3(60.96,97.79) v3(60.96,91.44) v3(60.96,86.36) v3(60.96,81.28) v3(60.96,71.12) v3(60.96,66.04) v3(60.96,35.56) v3(60.96,30.48) v3(60.96,25.4) v3(60.96,20.32) v3(60.96,15.24) v3(60.96,10.16) v3(60.96,5.08) v3(60.96,1.65) v3(66.04,315.85) v3(66.04,309.88) v3(66.04,279.4) v3(66.04,274.32) v3(66.04,269.24) v3(66.04,264.16) v3(66.04,259.08) v3(66.04,254) v3(66.04,248.92) v3(66.04,208.28) v3(66.04,203.2) v3(66.04,198.12) v3(66.04,193.04) v3(66.04,187.96) v3(66.04,147.32) v3(66.04,142.24) v3(66.04,137.16) v3(66.04,132.08) v3(66.04,127) v3(66.04,86.36) v3(66.04,81.28) v3(66.04,71.12) v3(66.04,66.04) v3(66.04,20.32) v3(66.04,15.24) v3(66.04,10.16) v3(66.04,5.08) v3(66.04,1.65) v3(67.94,221.62) v3(67.94,219.71) v3(67.94,160.66) v3(67.94,158.75) v3(67.94,100.33) v3(67.94,98.42) v3(67.94,39.37) v3(67.94,36.83) v3(69.22,283.21) v3(69.22,280.67) v3(71.12,315.85) v3(71.12,309.88) v3(71.12,269.24) v3(71.12,259.08) v3(71.12,254) v3(71.12,248.92) v3(71.12,203.2) v3(71.12,193.04) v3(71.12,187.96) v3(71.12,127) v3(71.12,66.04) v3(71.12,10.16) v3(71.12,5.08) v3(71.12,1.65) v3(76.2,315.85) v3(76.2,309.88) v3(76.2,248.92) v3(76.2,187.96) v3(76.2,66.04) v3(76.2,5.08) v3(76.2,1.65) v3(81.28,315.85) v3(81.28,309.88) v3(81.28,304.8) v3(81.28,299.72) v3(81.28,294.64) v3(81.28,248.92) v3(81.28,243.84) v3(81.28,238.76) v3(81.28,233.68) v3(81.28,228.6) v3(81.28,187.96) v3(81.28,182.88) v3(81.28,177.8) v3(81.28,172.72) v3(81.28,127) v3(81.28,116.84) v3(81.28,111.76) v3(81.28,66.04) v3(81.28,60.96) v3(81.28,55.88) v3(81.28,50.8) v3(81.28,45.72) v3(81.28,5.08) v3(81.28,1.65) v3(86.36,315.85) v3(86.36,309.88) v3(86.36,304.8) v3(86.36,299.72) v3(86.36,294.64) v3(86.36,5.08) v3(86.36,1.65) v3(91.44,315.85) v3(91.44,309.88) v3(91.44,299.72) v3(91.44,294.64) v3(91.44,248.92) v3(91.44,243.84) v3(91.44,238.76) v3(91.44,233.68) v3(91.44,182.88) v3(91.44,177.8) v3(91.44,172.72) v3(91.44,127) v3(91.44,116.84) v3(91.44,111.76) v3(91.44,55.88) v3(91.44,50.8) v3(91.44,5.08) v3(91.44,1.65) v3(96.52,315.85) v3(96.52,309.88) v3(96.52,299.72) v3(96.52,294.64) v3(96.52,248.92) v3(96.52,238.76) v3(96.52,233.68) v3(96.52,228.6) v3(96.52,177.8) v3(96.52,172.72) v3(96.52,167.64) v3(96.52,116.84) v3(96.52,111.76) v3(96.52,106.68) v3(96.52,55.88) v3(96.52,50.8) v3(96.52,45.72) v3(96.52,5.08) v3(96.52,1.65) v3(101.6,315.85) v3(101.6,309.88) v3(101.6,299.72) v3(101.6,294.64) v3(101.6,248.92) v3(101.6,243.84) v3(101.6,238.76) v3(101.6,233.68) v3(101.6,182.88) v3(101.6,177.8) v3(101.6,172.72) v3(101.6,116.84) v3(101.6,111.76) v3(101.6,55.88) v3(101.6,50.8) v3(101.6,5.08) v3(101.6,1.65) v3(106.68,315.85) v3(106.68,309.88) v3(106.68,304.8) v3(106.68,299.72) v3(106.68,294.64) v3(106.68,243.84) v3(106.68,238.76) v3(106.68,233.68) v3(106.68,187.96) v3(106.68,182.88) v3(106.68,177.8) v3(106.68,172.72) v3(106.68,127) v3(106.68,116.84) v3(106.68,111.76) v3(106.68,60.96) v3(106.68,55.88) v3(106.68,50.8) v3(106.68,1.65) v3(109.22,274.95) v3(109.22,214) v3(109.22,153.03) v3(109.22,92.08) v3(109.22,31.11) v3(110.49,92.08) v3(111.12,274.95) v3(111.12,214) v3(111.12,153.03) v3(111.12,31.11) v3(111.76,315.85) v3(111.76,309.88) v3(111.76,304.8) v3(111.76,299.72) v3(111.76,294.64) v3(111.76,269.24) v3(111.76,243.84) v3(111.76,238.76) v3(111.76,233.68) v3(111.76,182.88) v3(111.76,177.8) v3(111.76,172.72) v3(111.76,144.78) v3(111.76,127) v3(111.76,116.84) v3(111.76,111.76) v3(111.76,88.9) v3(111.76,60.96) v3(111.76,55.88) v3(111.76,50.8) v3(111.76,27.94) v3(111.76,1.65) v3(113.03,266.7) v3(114.17,198.5) v3(114.3,210.82) v3(114.3,147.32) v3(116.84,315.85) v3(116.84,309.88) v3(116.84,304.8) v3(116.84,299.72) v3(116.84,294.64) v3(116.84,269.24) v3(116.84,243.84) v3(116.84,238.76) v3(116.84,233.68) v3(116.84,182.88) v3(116.84,177.8) v3(116.84,172.72) v3(116.84,116.84) v3(116.84,111.76) v3(116.84,88.9) v3(116.84,81.28) v3(116.84,60.96) v3(116.84,55.88) v3(116.84,50.8) v3(116.84,27.94) v3(116.84,20.32) v3(116.84,1.65) v3(119.38,210.82) v3(121.92,315.85) v3(121.92,309.88) v3(121.92,304.8) v3(121.92,299.72) v3(121.92,269.24) v3(121.92,264.16) v3(121.92,238.76) v3(121.92,187.96) v3(121.92,177.8) v3(121.92,55.88) v3(121.92,50.8) v3(121.92,5.08) v3(121.92,1.65) v3(124.21,297.94) v3(124.21,296.42) v3(124.21,294.89) v3(124.21,236.98) v3(124.21,235.46) v3(124.21,233.93) v3(124.21,176.02) v3(124.21,174.5) v3(124.21,172.97) v3(124.21,115.06) v3(124.21,113.54) v3(124.21,112.01) v3(124.21,54.1) v3(124.21,52.58) v3(124.21,51.05) v3(127,315.85) v3(127,309.88) v3(127,304.8) v3(127,259.08) v3(127,254) v3(127,248.92) v3(127,243.84) v3(127,198.12) v3(127,193.04) v3(127,187.96) v3(127,182.88) v3(127,132.08) v3(127,76.2) v3(127,71.12) v3(127,66.04) v3(127,15.24) v3(127,10.16) v3(127,5.08) v3(127,1.65) v3(127.25,297.94) v3(127.25,296.42) v3(127.25,294.89) v3(127.25,236.98) v3(127.25,235.46) v3(127.25,233.93) v3(127.25,176.02) v3(127.25,174.5) v3(127.25,172.97) v3(127.25,115.06) v3(127.25,113.54) v3(127.25,112.01) v3(127.25,54.1) v3(127.25,52.58) v3(127.25,51.05) v3(132.08,315.85) v3(132.08,309.88) v3(132.08,304.8) v3(132.08,299.72) v3(132.08,269.24) v3(132.08,264.16) v3(132.08,259.08) v3(132.08,254) v3(132.08,248.92) v3(132.08,243.84) v3(132.08,238.76) v3(132.08,198.12) v3(132.08,193.04) v3(132.08,187.96) v3(132.08,182.88) v3(132.08,86.36) v3(132.08,81.28) v3(132.08,76.2) v3(132.08,71.12) v3(132.08,66.04) v3(132.08,60.96) v3(132.08,55.88) v3(132.08,25.4) v3(132.08,20.32) v3(132.08,15.24) v3(132.08,10.16) v3(132.08,5.08) v3(132.08,1.65) v3(135.64,297.94) v3(135.64,296.42) v3(135.64,294.89) v3(135.64,236.98) v3(135.64,235.46) v3(135.64,233.93) v3(135.64,176.02) v3(135.64,174.5) v3(135.64,172.97) v3(135.64,115.06) v3(135.64,113.54) v3(135.64,112.01) v3(135.64,54.1) v3(135.64,52.58) v3(135.64,51.05) v3(137.16,315.85) v3(137.16,309.88) v3(137.16,304.8) v3(137.16,269.24) v3(137.16,264.16) v3(137.16,208.28) v3(137.16,198.12) v3(137.16,66.04) v3(137.16,25.4) v3(137.16,20.32) v3(137.16,15.24) v3(137.16,10.16) v3(137.16,5.08) v3(137.16,1.65) v3(137.79,244.6) v3(137.79,62.87) v3(137.79,61.59) v3(138.43,196.47) v3(138.43,193.42) v3(138.56,185.04) v3(138.56,182.12) v3(138.56,75.18) v3(138.56,72.14) v3(138.68,297.94) v3(138.68,296.42) v3(138.68,294.89) v3(138.68,236.98) v3(138.68,235.46) v3(138.68,233.93) v3(138.68,176.02) v3(138.68,174.5) v3(138.68,172.97) v3(138.68,124.08) v3(138.68,121.03) v3(138.68,115.06) v3(138.68,113.54) v3(138.68,112.01) v3(138.68,54.1) v3(138.68,52.58) v3(138.68,51.05) v3(138.94,246) v3(138.94,242.95) v3(139.06,257.43) v3(139.06,254.38) v3(139.19,63.75) v3(139.32,135.76) v3(139.95,124.08) v3(139.95,121.03) v3(140.08,75.18) v3(140.08,72.14) v3(140.21,196.47) v3(140.21,193.42) v3(140.21,185.04) v3(140.21,182.12) v3(140.34,135.76) v3(140.34,63.75) v3(140.46,246) v3(140.59,257.43) v3(140.59,254.38) v3(140.72,60.71) v3(141.1,124.08) v3(141.1,121.03) v3(141.6,75.18) v3(141.6,72.14) v3(141.73,60.71) v3(141.86,185.04) v3(141.86,182.12) v3(141.99,246) v3(141.99,242.95) v3(142.11,257.43) v3(142.11,254.38) v3(142.11,196.47) v3(142.11,193.42) v3(142.24,315.85) v3(142.24,309.88) v3(142.24,304.8) v3(142.24,299.72) v3(142.24,274.32) v3(142.24,269.24) v3(142.24,264.16) v3(142.24,238.76) v3(142.24,213.36) v3(142.24,208.28) v3(142.24,198.12) v3(142.24,91.44) v3(142.24,66.04) v3(142.24,55.88) v3(142.24,30.48) v3(142.24,25.4) v3(142.24,20.32) v3(142.24,15.24) v3(142.24,10.16) v3(142.24,5.08) v3(142.24,1.65) v3(142.88,135) v3(142.88,133.99) v3(142.88,132.97) v3(147.07,297.81) v3(147.07,296.29) v3(147.07,294.77) v3(147.32,315.85) v3(147.32,309.88) v3(147.32,304.8) v3(147.32,299.72) v3(147.32,30.48) v3(147.32,25.4) v3(147.32,20.32) v3(147.32,15.24) v3(147.32,10.16) v3(147.32,6.99) v3(150.11,297.81) v3(150.11,296.29) v3(150.11,294.77) v3(152.4,315.85) v3(152.4,309.88) v3(152.4,304.8) v3(152.4,299.72) v3(152.4,30.48) v3(152.4,25.4) v3(152.4,20.32) v3(152.4,15.24) v3(152.4,10.16) v3(152.4,6.99) v3(157.48,315.85) v3(157.48,309.88) v3(157.48,304.8) v3(157.48,299.72) v3(157.48,30.48) v3(157.48,25.4) v3(157.48,20.32) v3(157.48,15.24) v3(157.48,10.16) v3(157.48,6.99) v3(158.5,297.81) v3(158.5,296.29) v3(158.5,294.77) v3(161.54,297.81) v3(161.54,296.29) v3(161.54,294.77) v3(162.56,315.85) v3(162.56,309.88) v3(162.56,304.8) v3(162.56,299.72) v3(162.56,30.48) v3(162.56,25.4) v3(162.56,20.32) v3(162.56,15.24) v3(162.56,10.16) v3(162.56,6.99) v3(167.64,315.85) v3(167.64,309.88) v3(167.64,304.8) v3(167.64,299.72) v3(167.64,294.64) v3(167.64,30.48) v3(167.64,25.4) v3(167.64,20.32) v3(167.64,15.24) v3(167.64,10.16) v3(167.64,6.99) v3(172.72,315.85) v3(172.72,309.88) v3(172.72,304.8) v3(172.72,299.72) v3(172.72,294.64) v3(172.72,289.56) v3(172.72,284.48) v3(172.72,279.4) v3(172.72,274.32) v3(172.72,269.24) v3(172.72,264.16) v3(172.72,259.08) v3(172.72,254) v3(172.72,248.92) v3(172.72,243.84) v3(172.72,238.76) v3(172.72,233.68) v3(172.72,228.6) v3(172.72,223.52) v3(172.72,218.44) v3(172.72,213.36) v3(172.72,203.2) v3(172.72,149.86) v3(172.72,147.32) v3(172.72,134.62) v3(172.72,132.08) v3(172.72,127) v3(172.72,124.46) v3(172.72,111.76) v3(172.72,109.22) v3(172.72,106.68) v3(172.72,101.6) v3(172.72,96.52) v3(172.72,91.44) v3(172.72,86.36) v3(172.72,81.28) v3(172.72,71.12) v3(172.72,66.04) v3(172.72,55.88) v3(172.72,50.8) v3(172.72,45.72) v3(172.72,40.64) v3(172.72,35.56) v3(172.72,30.48) v3(172.72,25.4) v3(172.72,20.32) v3(172.72,15.24) v3(172.72,10.16) v3(172.72,1.65) v3(175.26,149.86) v3(175.26,147.32) v3(175.26,134.62) v3(175.26,132.08) v3(175.26,127) v3(175.26,124.46) v3(175.26,111.76) v3(175.26,109.22) v3(177.8,304.8) v3(177.8,299.72) v3(177.8,294.64) v3(177.8,289.56) v3(177.8,284.48) v3(177.8,279.4) v3(177.8,274.32) v3(177.8,269.24) v3(177.8,264.16) v3(177.8,254) v3(177.8,248.92) v3(177.8,243.84) v3(177.8,238.76) v3(177.8,228.6) v3(177.8,218.44) v3(177.8,208.28) v3(177.8,203.2) v3(177.8,149.86) v3(177.8,147.32) v3(177.8,134.62) v3(177.8,132.08) v3(177.8,127) v3(177.8,124.46) v3(177.8,111.76) v3(177.8,109.22) v3(177.8,106.68) v3(177.8,101.6) v3(177.8,91.44) v3(177.8,86.36) v3(177.8,81.28) v3(177.8,71.12) v3(177.8,66.04) v3(177.8,50.8) v3(177.8,45.72) v3(177.8,40.64) v3(177.8,35.56) v3(177.8,30.48) v3(177.8,15.24) v3(180.34,149.86) v3(180.34,147.32) v3(180.34,134.62) v3(180.34,132.08) v3(180.34,127) v3(180.34,124.46) v3(180.34,111.76) v3(180.34,109.22) v3(183.77,307.47) v3(183.77,302.39) v3(183.77,297.31) v3(183.77,292.23) v3(183.77,287.15) v3(183.77,282.07) v3(183.77,276.99) v3(183.77,271.91) v3(183.77,266.83) v3(183.77,261.75) v3(183.77,256.67) v3(183.77,251.59) v3(183.77,246.51) v3(183.77,241.43) v3(183.77,231.27) v3(183.77,226.19) v3(183.77,221.11) v3(183.77,216.03) v3(183.77,210.95) v3(183.77,205.87) v3(183.77,200.79) v3(183.77,195.71) v3(183.77,190.63) v3(183.77,185.55) v3(183.77,180.47) v3(183.77,175.39) v3(183.77,170.31) v3(183.77,165.23) v3(183.77,160.15) v3(183.77,155.07) v3(183.77,149.99) v3(183.77,144.91) v3(183.77,139.83) v3(183.77,134.75) v3(183.77,129.67) v3(183.77,124.59) v3(183.77,119.51) v3(183.77,114.43) v3(183.77,109.35) v3(183.77,104.27) v3(183.77,99.19) v3(183.77,94.11) v3(183.77,89.03) v3(183.77,83.95) v3(183.77,78.87) v3(183.77,73.79) v3(183.77,68.71) v3(183.77,63.63) v3(183.77,58.55) v3(183.77,53.47) v3(183.77,48.39) v3(183.77,43.31) v3(183.77,38.23) v3(183.77,33.15) v3(183.77,28.07) v3(183.77,22.99) v3(183.77,17.91) v3(183.77,12.83) v3(183.77,7.75)
